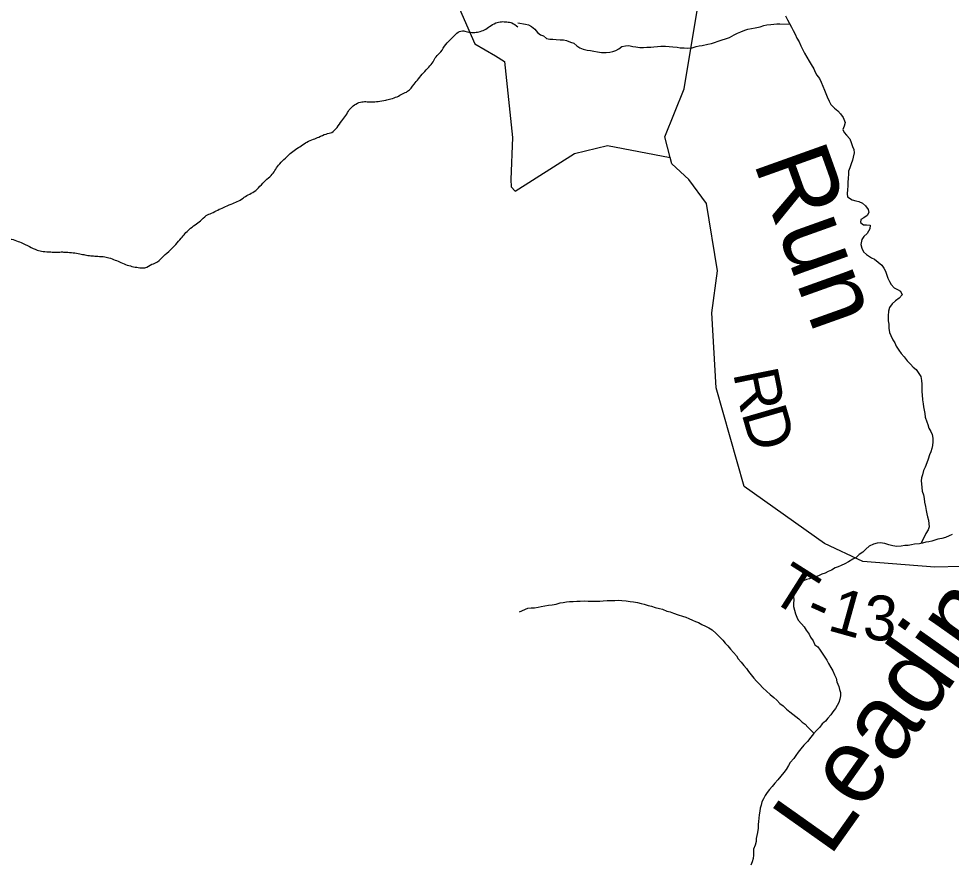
# Model space of a CAD drawing. Extents: x -15 to 405, y -40 to 87.
# Drawn here: x 6.81 to 7.989, y 16.197 to 17.266 of the extents above; entities that cross this region are included whole.
import ezdxf

# ---------------------------------------------------------------- set-up
doc = ezdxf.new("R2010")
doc.units = 0
for name, color, linetype in [('GM_P_State_Location', 7, 'Continuous'), ('GM_X_Adjacent_County_Text', 7, 'Continuous'), ('GM_X_Minor_Lake_Text', 7, 'Continuous'), ('GM_X_Minor_River', 7, 'Continuous')]:
    doc.layers.add(name, color=color, linetype=linetype)

msp = doc.modelspace()

# ---------------------------------------------------------------- linework, layer by layer
at = {"layer": 'GM_P_State_Location'}
for points in [[(8.0014, 16.5732), (7.9682, 16.5725), (7.8772, 16.5798), (7.8287, 16.6024), (7.7272, 16.6746), (7.692, 16.7991), (7.6864, 16.8939), (7.6934, 16.9472), (7.6795, 17.0324), (7.6572, 17.0626), (7.636, 17.0824), (7.6339, 17.0904), (7.6269, 17.1165), (7.6513, 17.1775), (7.6706, 17.2943), (7.6834, 17.3696), (7.6671, 17.5065), (7.6183, 17.5496), (7.531, 17.6132), (7.5192, 17.6499), (7.5184, 17.8591), (7.4525, 18.0102), (7.4996, 18.4039)], [(7.3468, 17.326), (7.3869, 17.2342), (7.413, 17.2189), (7.4241, 17.2118), (7.4346, 17.1159), (7.4322, 17.0627), (7.4327, 17.0532), (7.4376, 17.0479), (7.5128, 17.0955), (7.5545, 17.1058), (7.6339, 17.0904)]]:
    msp.add_lwpolyline(points, dxfattribs=at)
at = {"layer": 'GM_X_Adjacent_County_Text'}
for points in [[(7.441, 17.2609), (7.451, 17.2591), (7.4548, 17.2583), (7.4586, 17.2561), (7.4628, 17.2526), (7.4658, 17.2485), (7.4696, 17.2458), (7.4734, 17.2443), (7.4772, 17.2409), (7.4814, 17.2402), (7.4856, 17.2402), (7.4894, 17.2398), (7.4947, 17.2391), (7.4989, 17.2391), (7.5027, 17.2383), (7.5076, 17.2364), (7.5118, 17.2349), (7.5156, 17.2315), (7.5194, 17.2293), (7.5236, 17.2274), (7.5289, 17.2263), (7.5331, 17.2259), (7.5373, 17.2248), (7.5418, 17.224), (7.5471, 17.2233), (7.5528, 17.2233), (7.5574, 17.2237), (7.5612, 17.2244), (7.565, 17.226), (7.5688, 17.2279), (7.5726, 17.2309), (7.5771, 17.2317), (7.5813, 17.2321), (7.5866, 17.2309), (7.5904, 17.2306), (7.5954, 17.2298), (7.5999, 17.2298), (7.6041, 17.2302), (7.6094, 17.2302), (7.6132, 17.2306), (7.6178, 17.231), (7.6219, 17.2314), (7.628, 17.2311), (7.6326, 17.2307), (7.6371, 17.2303), (7.6424, 17.2299), (7.6462, 17.2292), (7.6516, 17.2292), (7.6561, 17.2288), (7.6614, 17.2292), (7.6664, 17.2308), (7.6705, 17.2315), (7.6743, 17.2323), (7.6815, 17.2338), (7.6861, 17.2346), (7.6899, 17.2358), (7.6944, 17.2377), (7.6994, 17.2392), (7.7035, 17.2407), (7.7085, 17.2423), (7.7145, 17.2457), (7.7187, 17.2476), (7.7229, 17.2495), (7.7282, 17.2514), (7.732, 17.2526), (7.7365, 17.2537), (7.7411, 17.2545), (7.7476, 17.2556), (7.7521, 17.2575), (7.7559, 17.2583), (7.7608, 17.2587), (7.7646, 17.2591), (7.7684, 17.2595), (7.7722, 17.2595), (7.785, 17.2589)], [(7.7794, 17.2698), (7.7821, 17.2644), (7.7844, 17.2599), (7.787, 17.2554), (7.7893, 17.2512), (7.7916, 17.2463), (7.7939, 17.2413), (7.7966, 17.2368), (7.7989, 17.2315), (7.8008, 17.2273), (7.8035, 17.2224), (7.8065, 17.2175), (7.8092, 17.2125), (7.8119, 17.208), (7.8153, 17.2027), (7.8172, 17.1985), (7.8191, 17.1947), (7.8225, 17.1902), (7.8245, 17.1856), (7.8267, 17.1807), (7.8287, 17.1758), (7.8306, 17.1716), (7.8321, 17.1674), (7.8348, 17.1618), (7.8367, 17.1576), (7.8413, 17.1527), (7.8458, 17.1496), (7.8489, 17.1459), (7.8523, 17.1409), (7.855, 17.1349), (7.8538, 17.1303), (7.852, 17.1261), (7.8535, 17.1223), (7.8565, 17.1186), (7.8607, 17.114), (7.8623, 17.1095), (7.8642, 17.1045), (7.8657, 17.1004), (7.8661, 17.0966), (7.865, 17.0909), (7.8642, 17.0871), (7.8623, 17.0825), (7.8608, 17.0776), (7.8593, 17.073), (7.8593, 17.0692), (7.8586, 17.0647), (7.8582, 17.0586), (7.8582, 17.0544), (7.8579, 17.0499), (7.8575, 17.0446), (7.8579, 17.0408), (7.8636, 17.037), (7.8682, 17.0359), (7.8723, 17.0347), (7.8769, 17.0329), (7.8807, 17.0294), (7.8838, 17.0249), (7.8849, 17.0211), (7.8826, 17.0173), (7.8785, 17.0143), (7.8747, 17.012), (7.8743, 17.0082), (7.8781, 17.0052), (7.8819, 17.0055), (7.8865, 17.0048), (7.8861, 17.0002), (7.8827, 16.9945), (7.8785, 16.9907), (7.8759, 16.9866), (7.8748, 16.9805), (7.8759, 16.9759), (7.8782, 16.9714), (7.882, 16.968), (7.8881, 16.9638), (7.8919, 16.9619), (7.8968, 16.9582), (7.9014, 16.9544), (7.9037, 16.9506), (7.906, 16.9468), (7.9071, 16.943), (7.9087, 16.9381), (7.911, 16.9335), (7.9129, 16.9297), (7.9167, 16.9256), (7.9209, 16.9237), (7.9247, 16.9214), (7.927, 16.9169), (7.9232, 16.9127), (7.9186, 16.9093), (7.9145, 16.9055), (7.9111, 16.9009), (7.9095, 16.896), (7.9092, 16.8903), (7.9092, 16.8838), (7.91, 16.8796), (7.91, 16.8747), (7.9108, 16.8694), (7.9127, 16.8656), (7.9153, 16.8599), (7.9176, 16.8561), (7.9195, 16.852)], [(7.9195, 16.852), (7.9226, 16.8467), (7.9256, 16.8425), (7.9295, 16.8383), (7.9333, 16.8334), (7.9375, 16.8292), (7.9409, 16.8255), (7.9447, 16.8224), (7.9481, 16.8175), (7.9504, 16.8137), (7.9516, 16.8084), (7.952, 16.8039), (7.952, 16.7993), (7.952, 16.794), (7.9524, 16.7902), (7.9528, 16.7841), (7.9535, 16.7792), (7.9539, 16.7754), (7.9547, 16.7709), (7.9555, 16.7667), (7.9562, 16.7621), (7.9582, 16.7564), (7.9593, 16.7527), (7.9605, 16.7481), (7.9631, 16.7439), (7.9647, 16.7401), (7.9658, 16.7356), (7.9658, 16.731), (7.9655, 16.7265), (7.9643, 16.7223), (7.9632, 16.7185), (7.9617, 16.7143), (7.9598, 16.709), (7.9583, 16.7045), (7.956, 16.6991), (7.9541, 16.6946), (7.9526, 16.6893), (7.9515, 16.6855), (7.9508, 16.6817), (7.9512, 16.6779), (7.9519, 16.6733), (7.9523, 16.6684), (7.9539, 16.6639), (7.9546, 16.6593), (7.9554, 16.6548), (7.9566, 16.6491), (7.9573, 16.6441), (7.9581, 16.64), (7.9589, 16.6362), (7.9604, 16.632), (7.9608, 16.6271), (7.9612, 16.6233), (7.96, 16.6195), (7.957, 16.6149), (7.9551, 16.6111), (7.9505, 16.6023)], [(7.9901, 16.6139), (7.9863, 16.612), (7.9817, 16.61), (7.9772, 16.6089), (7.9722, 16.6077), (7.9684, 16.6066), (7.9646, 16.6054), (7.9605, 16.6043), (7.9567, 16.6039), (7.9525, 16.6028), (7.9487, 16.602), (7.9426, 16.6016), (7.9388, 16.6008), (7.9347, 16.5997), (7.9305, 16.5997), (7.9259, 16.5989), (7.9202, 16.5985), (7.9153, 16.5996), (7.91, 16.6008), (7.905, 16.6023), (7.8993, 16.6034), (7.8952, 16.603), (7.8906, 16.6015), (7.8853, 16.5988), (7.8811, 16.595), (7.8773, 16.5916), (7.8728, 16.5885), (7.8686, 16.5843), (7.8645, 16.5824), (7.8592, 16.579), (7.8546, 16.5767), (7.85, 16.5744), (7.8459, 16.5729), (7.8421, 16.5718), (7.8375, 16.5687), (7.8334, 16.5668), (7.8296, 16.5649), (7.8254, 16.5634), (7.8212, 16.5615), (7.8174, 16.5603), (7.8136, 16.5592), (7.8098, 16.5576), (7.806, 16.5569), (7.8023, 16.555), (7.7985, 16.5519), (7.7951, 16.5481), (7.7924, 16.5439), (7.7905, 16.539), (7.7898, 16.5352), (7.7902, 16.5306), (7.7898, 16.5268), (7.7898, 16.5227), (7.791, 16.5181), (7.7921, 16.5136), (7.794, 16.5094), (7.7956, 16.5056), (7.7997, 16.5007), (7.8032, 16.4969), (7.8058, 16.4927), (7.8093, 16.4878), (7.8112, 16.484), (7.8146, 16.4791), (7.8165, 16.4742), (7.8203, 16.4719), (7.8234, 16.4674), (7.8283, 16.4598), (7.8318, 16.4549), (7.8337, 16.4507), (7.8367, 16.4454), (7.8394, 16.4412), (7.8413, 16.4363), (7.8436, 16.4321), (7.8444, 16.4276), (7.8467, 16.4215), (7.8478, 16.4177), (7.849, 16.4139), (7.849, 16.4098), (7.8482, 16.4056), (7.8467, 16.4014), (7.8448, 16.3976), (7.8426, 16.3938), (7.8395, 16.3896), (7.8369, 16.3858), (7.8331, 16.3816), (7.8301, 16.3778), (7.8259, 16.3744), (7.8229, 16.3702), (7.8187, 16.3657), (7.8149, 16.3615)], [(7.4431, 16.5161), (7.4538, 16.5207), (7.4579, 16.5211), (7.4621, 16.5211), (7.4667, 16.5219), (7.4708, 16.5226), (7.4754, 16.5234), (7.4799, 16.5242), (7.4845, 16.5249), (7.4894, 16.5257), (7.4947, 16.5272), (7.4985, 16.5276), (7.5027, 16.5284), (7.5065, 16.5292), (7.5111, 16.5292), (7.5156, 16.5296), (7.5198, 16.5296), (7.5255, 16.53), (7.5301, 16.5296), (7.5361, 16.5296), (7.5407, 16.5296), (7.5449, 16.5293), (7.549, 16.53), (7.554, 16.5301), (7.5593, 16.5301), (7.5639, 16.5301), (7.568, 16.5308), (7.5726, 16.5305), (7.5779, 16.5297), (7.5832, 16.529), (7.5874, 16.5286), (7.5923, 16.5279), (7.5969, 16.5267), (7.6007, 16.5256), (7.606, 16.5241), (7.6102, 16.523), (7.6148, 16.5215), (7.6201, 16.52), (7.6239, 16.5192), (7.6296, 16.517), (7.6338, 16.5158), (7.6379, 16.5143), (7.644, 16.5121), (7.6493, 16.5106), (7.6535, 16.5091), (7.6573, 16.5075), (7.6619, 16.5053), (7.6657, 16.5038), (7.6695, 16.5023), (7.6737, 16.5), (7.6782, 16.4977), (7.6824, 16.4958), (7.6866, 16.4932), (7.6919, 16.4887), (7.6965, 16.4841), (7.7003, 16.4803), (7.7034, 16.4765), (7.7064, 16.4728), (7.7098, 16.4686), (7.7136, 16.4644), (7.7175, 16.4603), (7.7197, 16.4565), (7.7236, 16.4523), (7.727, 16.4481), (7.73, 16.4444), (7.7327, 16.4406), (7.7361, 16.4364), (7.7396, 16.4322), (7.743, 16.4281), (7.7468, 16.4247), (7.751, 16.4197), (7.7556, 16.4156), (7.7601, 16.4114), (7.7647, 16.4076), (7.7685, 16.4042), (7.7723, 16.4001), (7.7765, 16.397), (7.7807, 16.3929), (7.7849, 16.3895), (7.7887, 16.3865), (7.7925, 16.3834), (7.7963, 16.3808), (7.8005, 16.3766), (7.8043, 16.374), (7.8077, 16.3702), (7.8157, 16.3623)], [(7.8149, 16.3615), (7.8115, 16.3573), (7.8074, 16.352), (7.8028, 16.3474), (7.7987, 16.3428), (7.7953, 16.3383), (7.7926, 16.3341), (7.79, 16.3303), (7.7854, 16.3254), (7.7831, 16.3216), (7.7805, 16.3166), (7.7775, 16.3128), (7.7737, 16.3083), (7.7699, 16.3037), (7.7661, 16.2991), (7.7627, 16.2953), (7.7593, 16.2915), (7.7563, 16.2873), (7.7536, 16.2835), (7.7517, 16.2797), (7.7495, 16.2756), (7.7487, 16.2714), (7.7476, 16.2676), (7.7472, 16.2638), (7.7461, 16.2592), (7.7457, 16.2551), (7.7454, 16.2509), (7.745, 16.2471), (7.745, 16.2422), (7.7439, 16.2368), (7.7431, 16.233), (7.7424, 16.2293), (7.7424, 16.2255), (7.7413, 16.2209), (7.739, 16.216), (7.739, 16.2122), (7.739, 16.2084), (7.7387, 16.2042), (7.7372, 16.2), (7.7356, 16.1958)]]:
    msp.add_lwpolyline(points, dxfattribs=at)
for points in [[(7.0938, 17.039), (7.1004, 17.0433), (7.1078, 17.0473), (7.1152, 17.0542), (7.1223, 17.0616), (7.1293, 17.0678), (7.1341, 17.0741), (7.1385, 17.0808), (7.1455, 17.0878), (7.1534, 17.0955), (7.16, 17.1006), (7.1674, 17.1053), (7.1744, 17.11), (7.1828, 17.1136), (7.1894, 17.1164), (7.199, 17.1202), (7.2059, 17.1223), (7.2126, 17.1285), (7.2185, 17.1367), (7.2237, 17.1437), (7.2281, 17.1508), (7.2348, 17.157), (7.2421, 17.1606), (7.2489, 17.1611), (7.2565, 17.1609), (7.2645, 17.1614), (7.2741, 17.163), (7.2806, 17.1647), (7.2886, 17.1674), (7.2952, 17.171), (7.3018, 17.1742), (7.31, 17.1831), (7.3156, 17.1901), (7.3219, 17.1975), (7.3286, 17.2049), (7.3341, 17.2115), (7.3378, 17.2179), (7.3437, 17.2241), (7.35, 17.2334), (7.3571, 17.2408), (7.3642, 17.2478), (7.3711, 17.2506), (7.3775, 17.2496), (7.3851, 17.2486), (7.3919, 17.2495), (7.3989, 17.2519), (7.4055, 17.2563), (7.4132, 17.2606), (7.4205, 17.2622), (7.4273, 17.262), (7.4337, 17.2606), (7.4411, 17.2558)], [(6.349, 16.9569), (6.3567, 16.962), (6.3632, 16.964), (6.3712, 16.9642), (6.3785, 16.9654), (6.3877, 16.9697), (6.3947, 16.9725), (6.4032, 16.9783), (6.4102, 16.9834), (6.4176, 16.9885), (6.4231, 16.9955), (6.4306, 17.004), (6.4362, 17.0106), (6.4425, 17.0176), (6.4522, 17.0261), (6.4593, 17.0323), (6.4674, 17.0385), (6.4783, 17.045), (6.4849, 17.0497), (6.4915, 17.0536), (6.4999, 17.0568), (6.508, 17.0611), (6.5146, 17.0628), (6.523, 17.0644), (6.5306, 17.0656), (6.5375, 17.0666), (6.5447, 17.0671), (6.5519, 17.0668), (6.5587, 17.0659), (6.5677, 17.0637), (6.5764, 17.0618), (6.5847, 17.06), (6.5915, 17.0579), (6.5986, 17.0565), (6.6058, 17.0555), (6.6129, 17.0534), (6.6193, 17.0517), (6.6261, 17.0499), (6.6344, 17.047), (6.6419, 17.0441), (6.6504, 17.0385), (6.6582, 17.0341), (6.6664, 17.0277), (6.6749, 17.0213), (6.6816, 17.0162), (6.6905, 17.0098), (6.6979, 17.0054), (6.7049, 16.9994), (6.7197, 16.9883), (6.7276, 16.9858), (6.736, 16.9863), (6.7425, 16.9879), (6.7506, 16.9903), (6.7597, 16.9919), (6.7662, 16.9925), (6.7745, 16.9926), (6.7818, 16.9923), (6.7893, 16.9906), (6.7957, 16.9888), (6.8055, 16.9859), (6.8133, 16.9829), (6.8238, 16.978), (6.8335, 16.9735), (6.841, 16.9718), (6.8509, 16.971), (6.8573, 16.9708), (6.8638, 16.971), (6.8702, 16.9708), (6.879, 16.9701), (6.8876, 16.9687), (6.894, 16.9673), (6.9016, 16.9663), (6.908, 16.9657), (6.9171, 16.9651), (6.9243, 16.9637), (6.9322, 16.9608), (6.9393, 16.9579), (6.9475, 16.9545), (6.9554, 16.9524), (6.9634, 16.951), (6.9698, 16.9511), (6.9787, 16.9554), (6.9856, 16.9586), (6.9931, 16.9656), (7.0021, 16.9736), (7.0088, 16.9806), (7.0155, 16.9884), (7.0257, 16.9995), (7.0331, 17.0053), (7.0401, 17.0104), (7.0472, 17.017), (7.0541, 17.0202), (7.0618, 17.0241), (7.0691, 17.0273), (7.0788, 17.0315), (7.0865, 17.0347), (7.0938, 17.039)]]:
    msp.add_spline(points, degree=3, dxfattribs=at)

# ---------------------------------------------------------------- texts
at = {"layer": 'GM_X_Minor_Lake_Text'}
for s, height, rotation, p in [('Run', 0.09471, 289.686, (7.7384, 17.0851)), ('Leading', 0.0947, 54.6919, (7.8351, 16.2047))]:
    msp.add_text(s, height=height, rotation=rotation, dxfattribs=at).set_placement(p)
at = {"layer": 'GM_X_Minor_River'}
for s, rotation, p in [('R', 281.4492, (7.713, 16.8181)), ('D', 286.2019, (7.7235, 16.7675)), ('T', 327.633, (7.7572, 16.5329)), ('1', 344.4218, (7.8309, 16.4932)), ('3', 355.1817, (7.8761, 16.4817)), ('-', 335.7427, (7.8008, 16.506))]:
    msp.add_text(s, height=0.0568, rotation=rotation, dxfattribs=at).set_placement(p)

doc.saveas('drawing.dxf')
